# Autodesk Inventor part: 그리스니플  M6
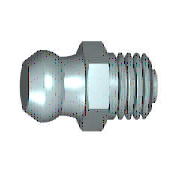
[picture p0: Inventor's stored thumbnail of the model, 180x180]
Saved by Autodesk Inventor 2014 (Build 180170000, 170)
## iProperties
IsCustomPart: 1
Created: 2012-02
Part Number: 그리스니플  M6
Material: 강철, 연강
Description: 그리스 니플에 대한 사양. 제I부: 버튼 머리 그리스 니플 유형 A
Document SubType Name: Modeling
Standard: IS 4009
Designer: mduedu
Standards Organization: IS
Language: ko-KR
Size Designation: M6 원추 짧은
Categories: <MemberInstance><Categories><Category DisplayName="기타 부품" InternalName="5aa15e00-363f-49f2-933f-16f664388e3f" Mnemonic="OTHER"><Category DisplayName="그리스 부속품" I
Density: 1 g/cm^3
Appearance: 강철
Author: mduedu
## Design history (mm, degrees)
sketch "스케치1"
  geometry: L1 (-9.8, 0)-(-9.8, 2.25); L2 (-9.8, 2.25)-(-8.055, 3.194); L3 (-9.8, 0)-(6.2, 0); L4 (6.2, 0)-(6.2, 1.5); L5 (6.2, 1.5)-(5.5, 1.5); L6 (5.5, 1.5)-(5.5, 3); L7 (5.5, 3)-(0, 3); L8 (-13, 0)-(9.4, 0) reference; L9 (0, -1.725)-(0, 10.35) reference; L10 (-3, 3.5)-(0, 3.5); L11 (0, 3.5)-(0, 3); A1 r 3.25 centre (-7.455, 0) between (-5.573, 2.65) and (-8.055, 3.194); A2 r 6 centre (-6.12, 8.625) between (-5.573, 2.65) and (-3, 3.5)
  constraints: 18 end point, 5 perpendicular, 4 point on circle, 2 centre point, 2 parallel, 2 point on line, 1 collinear, 1 vertical
  dimensions: "d0" = 16 distance between parallel lines of L1 L4 (= GL); "d1" = 5.3 diameter of A1.start L3 (= KGB2); "d2" = 0.7 distance between parallel lines of L4 L6 (= PHH); "d3" = 3 diameter of L5 L3 (= 0.5 x NND); "d4" = 6 diameter of L7 L3 (= NND); "d5" = 6.5 dimension on A1 L3 (= KR); "d6" = 4.5 diameter of L1.end L3 (= KGB1); "d7" = 6 radius of A2 (= RBN); "d11" = 7 diameter of L10.start L3 (= SW); "d14" = 3 distance of L10.start L10.end (= KOH); "d15" = 5.5 distance between parallel lines of L6 L11 (= NLG); "d61" = 8.05479 distance from line of L9 L2.end (computed from KGB1, KR, PHH, GL, NLG, VERS); "d62" = 7.45479 distance from line of L9 A1.centre (computed from NLG, GL, PHH, KR, KGB1)
revolve "본체" sketch "스케치1" stored, may be unused: angle "d25" = 90 deg
sketch "스케치2"
  geometry: L1 (2.021, 3.5)-(4.041, 0); L2 (4.041, 0)-(2.021, -3.5); L3 (2.021, -3.5)-(-2.021, -3.5); L4 (-2.021, -3.5)-(-4.041, 0); L5 (-4.041, 0)-(-2.021, 3.5); L6 (-2.021, 3.5)-(2.021, 3.5); C1 r 3.5 at (0, 0) reference; 1 further point
  constraints: 12 end point, 1 coincident, 1 horizontal, 1 tangent, 11 other
extrude "머리" join sketch "스케치2" distance "d17" = 3 (= KOH); taper "d18" = 0 deg
sketch "스케치3"
  geometry: L1 (2.687, 4.041)-(3, 4.041); L2 (3, 4.041)-(3, 3.5); L3 (3, 3.5)-(2.687, 4.041); L4 (0.313, 4.041)-(0, 4.041); L5 (0, 4.041)-(0, 3.5); L6 (0, 3.5)-(0.313, 4.041); L7 (3.6, 0)-(-0.6, 0) reference; L8 (0, 4.041)-(0, 2.021) reference; L9 (0, 4.041)-(3, 4.041) reference; L10 (3, 3.031)-(3, 4.041) reference
  constraints: 12 end point, 4 collinear, 3 perpendicular, 1 horizontal
  dimensions: "d19" = 3.5 distance from line of L5.end L7 (= 0.5 x SW); "d20" = 3.5 distance from line of L2.end L7 (= 0.5 x SW); "d21" = 30 deg angle of L6 L5; "d22" = 30 deg angle of L2 L3
revolve "모따기1" sketch "스케치3" stored, may be unused: angle "d56" = 90 deg
body "Solid1"
fillet "모깎기1" dims "d8" = 0.2 (= RR)
feature "스레드1" dims "d9" = 4.88655 (= NLG - GAL), "d10" = 0
chamfer "모따기2" distance "d23" = 0.61345 (= -0.5 x GD1 + 0.5 x NND); stored, may be unused: angle "d24" = 45 deg, second distance "d59" = 0.61345 (= -0.5 x GD1 + 0.5 x NND)
other parameters: "NLG" = 5.5 [user parameter; used in 4 equation terms], "GL" = 16 [user parameter; used in 3 equation terms], "NND" = 6 [user parameter; used in 4 equation terms], "KGB1" = 4.5 [user parameter; used in 3 equation terms], "KGB2" = 5.3 [user parameter; used in 1 equation term], "VERS" = 0.6 [user parameter; used in 1 equation term], "KR" = 6.5 [user parameter; used in 3 equation terms], "RBN" = 6 [user parameter; used in 1 equation term], "SW" = 7 [user parameter; used in 3 equation terms], "KOH" = 3 [user parameter; used in 2 equation terms], "GAL" = 0.61345 (= 0.61345 x PTC) [user parameter; used in 1 equation term], "FAWI" = 45 deg [user parameter], "PHH" = 0.7 [user parameter; used in 3 equation terms], "GD1" = 4.7731 (= THREADDIA - 1.2269 x PTC) [user parameter; used in 2 equation terms], "RR" = 0.2 [user parameter; used in 1 equation term], "d12" = 0, "d13" = 0, "GUL" = 0.61345 (= 0.61345 x PTC) [user parameter], "DULO" = 1.5 [user parameter], "PTC" = 1 [user parameter; used in 4 equation terms], "GEL" = 5.5 [user parameter], "THREADDIA" = 6 [user parameter; used in 1 equation term], "TOA" = 30 deg [user parameter]
